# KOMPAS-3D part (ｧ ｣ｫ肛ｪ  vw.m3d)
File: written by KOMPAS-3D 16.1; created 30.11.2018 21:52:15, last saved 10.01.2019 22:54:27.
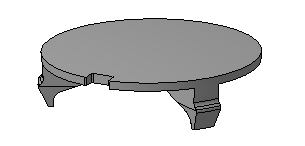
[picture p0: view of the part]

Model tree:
1. Эскиз:1
2. Операция вращения:1
     Угол 1 = 360
3. Смещенная плоскость:1
     Расстояние = 2.86
4. Эскиз:2
5. Вырезать элемент выдавливания:1
     Расстояние 1 = 5.5
6. Эскиз:3
7. Вырезать элемент выдавливания:2
     Расстояние 1 = 10
8. Эскиз:4
9. Вырезать элемент выдавливания:3
     Расстояние 2 = 30; Расстояние 1 = 10
10. Массив по концентрической сетке:1  (with: Вырезать элемент выдавливания:3)  (3 pattern instances)
     Геометрический массив = 2; Шаг 2 = 360
11. Эскиз:5
12. Скругление:4
     Радиус = 0.25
